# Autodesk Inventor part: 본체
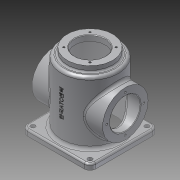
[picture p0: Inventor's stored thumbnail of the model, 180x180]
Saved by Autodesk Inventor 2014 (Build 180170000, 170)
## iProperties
Created: 2015-10
Part Number: 본체
Material: 알루미늄 6061
Document SubType Name: Modeling
Designer: Administrator
Density: 2.71 g/cm^3
Appearance: 알루미늄 - 평지
Mass: 951.24 g
Surface Area: 1038.7 cm^2
Volume: 351.011 cm^3
Author: Administrator
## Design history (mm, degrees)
sketch "스케치1"
  geometry: L1 (-60, 60)-(60, 60); L2 (60, 60)-(60, -60); L3 (60, -60)-(-60, -60); L4 (-60, -60)-(-60, 60); 3 further points
  constraints: 8 end point, 2 midpoint, 2 parallel, 1 horizontal, 1 horizontal alignment, 1 perpendicular, 1 vertical alignment
  dimensions: "d0" = 120 distance between parallel lines of L2 L4; "d1" = 120 distance between parallel lines of L3 L1
extrude "돌출1" new body sketch "스케치1" distance "d2" = 10; taper "d3" = 0 deg
sketch "스케치7"
  geometry: C1 r 50 at (0, 0); 1 further point
  constraints: 1 centre point, 1 coincident
  dimensions: "d11" = 100 diameter of C1
extrude "돌출4" join sketch "스케치7" distance "d12" = 110; taper "d13" = 0 deg
sketch "스케치8"
  geometry: C1 r 40 at (0, 0); 1 further point
  constraints: 1 centre point, 1 coincident
  dimensions: "d14" = 80 diameter of C1
extrude "돌출5" join sketch "스케치8" distance "d15" = 10; taper "d16" = 0 deg
feature "쉘5" dims "d37" = 10, "d38" = 5, "d115" = 5
sketch "스케치9"
  geometry: C1 r 27 at (0, 0); 1 further point
  constraints: 1 centre point, 1 coincident
  dimensions: "d23" = 54 diameter of C1
extrude "돌출6" cut sketch "스케치9" stored distance "d24" = 5; taper "d25" = 0 deg
node "작업 평면4"
  node "작업 평면3"
sketch "스케치13"
  geometry: L1 (60, 0)-(-60, 0) reference; C1 r 40 at (0, 60); 2 further points
  constraints: 1 centre point, 1 midpoint, 1 vertical alignment
  dimensions: "d49" = 80 diameter of C1; "d50" = 60 distance from line of L1 C1.centre
extrude "돌출7" join sketch "스케치13" stored distance "d51" = 5; taper "d52" = 0 deg
sketch "스케치14" dims "d54" = 65
  geometry: L1 (0, 0)-(-40, 0); L2 (0, 0)-(-28.284, 28.284); A1 r 40 centre (0, 0) between (-40, 0) and (-28.284, 28.284) reference; 3 further points
  constraints: 4 end point, 2 point on circle, 1 coincident, 1 horizontal, 1 point on line, 3 other
  dimensions: "d53" = 45 deg angle of L1 L2
hole "구멍1" sketch "스케치14" at (-22.981, 22.981) diameter "d55" = 3.459; stored, may be unused: countersink angle "d59" = 90 deg, drill point angle "d61" = 118 deg; dims "d56" = 8, "d57" = 4, "d58" = 2, "d60" = 10
sketch "스케치16"
  geometry: L1 (60, 0)-(-60, 0) reference; C1 r 27 at (0, 60); 1 further point
  constraints: 1 centre point, 1 vertical alignment
  dimensions: "d66" = 54 diameter of C1; "d67" = 60 distance from line of L1 C1.centre
extrude "돌출8" cut sketch "스케치16" stored distance "d68" = 5; taper "d69" = 0 deg
sketch "스케치18"
  geometry: L1 (0, 0)-(-40, 0); 2 further points
  constraints: 2 end point, 1 horizontal alignment, 1 point on line, 1 other
  dimensions: "d71" = 32.5 distance of L1.start point (-32.5, 0)
hole "구멍2" sketch "스케치18" at (-32.5, 0) diameter "d72" = 3.242; stored, may be unused: countersink angle "d76" = 90 deg, drill point angle "d78" = 118 deg; dims "d73" = 8, "d74" = 4, "d75" = 2, "d77" = 10
chamfer "모따기1" distance "d83" = 3; stored, may be unused: second distance "d84" = 2, angle "d85" = 45 deg
chamfer "모따기2" distance "d86" = 1; stored, may be unused: second distance "d87" = 2, angle "d88" = 45 deg
fillet "모깎기3" dims "d90" = 5
fillet "모깎기4" dims "d91" = 5
fillet "모깎기5" dims "d92" = 3
sketch "스케치19"
  geometry: C1 r 4 at (-50, -50); 1 further point
  constraints: 1 centre point
  dimensions: "d93" = 8 diameter of C1; "d94" = 50 horizontal distance of point (0, 0) C1.centre; "d95" = 50 horizontal distance of C1.centre point (0, 0)
extrude "돌출9" cut sketch "스케치19" distance "d96" = 10; taper "d97" = 0 deg
node "작업 평면8"
  node "작업 평면7"
sketch "스케치21"
  geometry: L1 (60, 0)-(-60, 0) reference; 3 further points
  constraints: 1 midpoint, 1 vertical alignment, 1 other
  dimensions: "d112" = 70 distance from line of L1 point (0, 70)
feature "엠보싱2" sketch "스케치21" dims "d0" = 120, "d1" = 120, "d106" = 0.5, "d107" = 0
fillet "모깎기7" dims "d108" = 10
fillet "모깎기8" dims "d109" = 3
fillet "모깎기9" dims "d110" = 5
fillet "모깎기10" dims "d111" = 5
node "솔리드1"
pattern_circular "원형 패턴1" dims angle "d63" = 360 deg
pattern_circular "원형 패턴2" dims angle "d80" = 360 deg
mirror "대칭1"
mirror "대칭2"
mirror "대칭3"
other parameters: "d47" = 90 deg, "d48" = 62, "d104" = 90 deg, "d105" = 50.5
